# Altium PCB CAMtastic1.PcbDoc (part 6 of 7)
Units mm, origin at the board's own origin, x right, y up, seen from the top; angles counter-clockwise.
Board outline 150.22 x 135.24 mm, 5 copper layers (Top Layer, Layer 1, Mid-Layer 1, Layer 2, Bottom Layer), stack 0.461 mm thick; 0 components, 362 nets, 2885 pads, 0 vias.
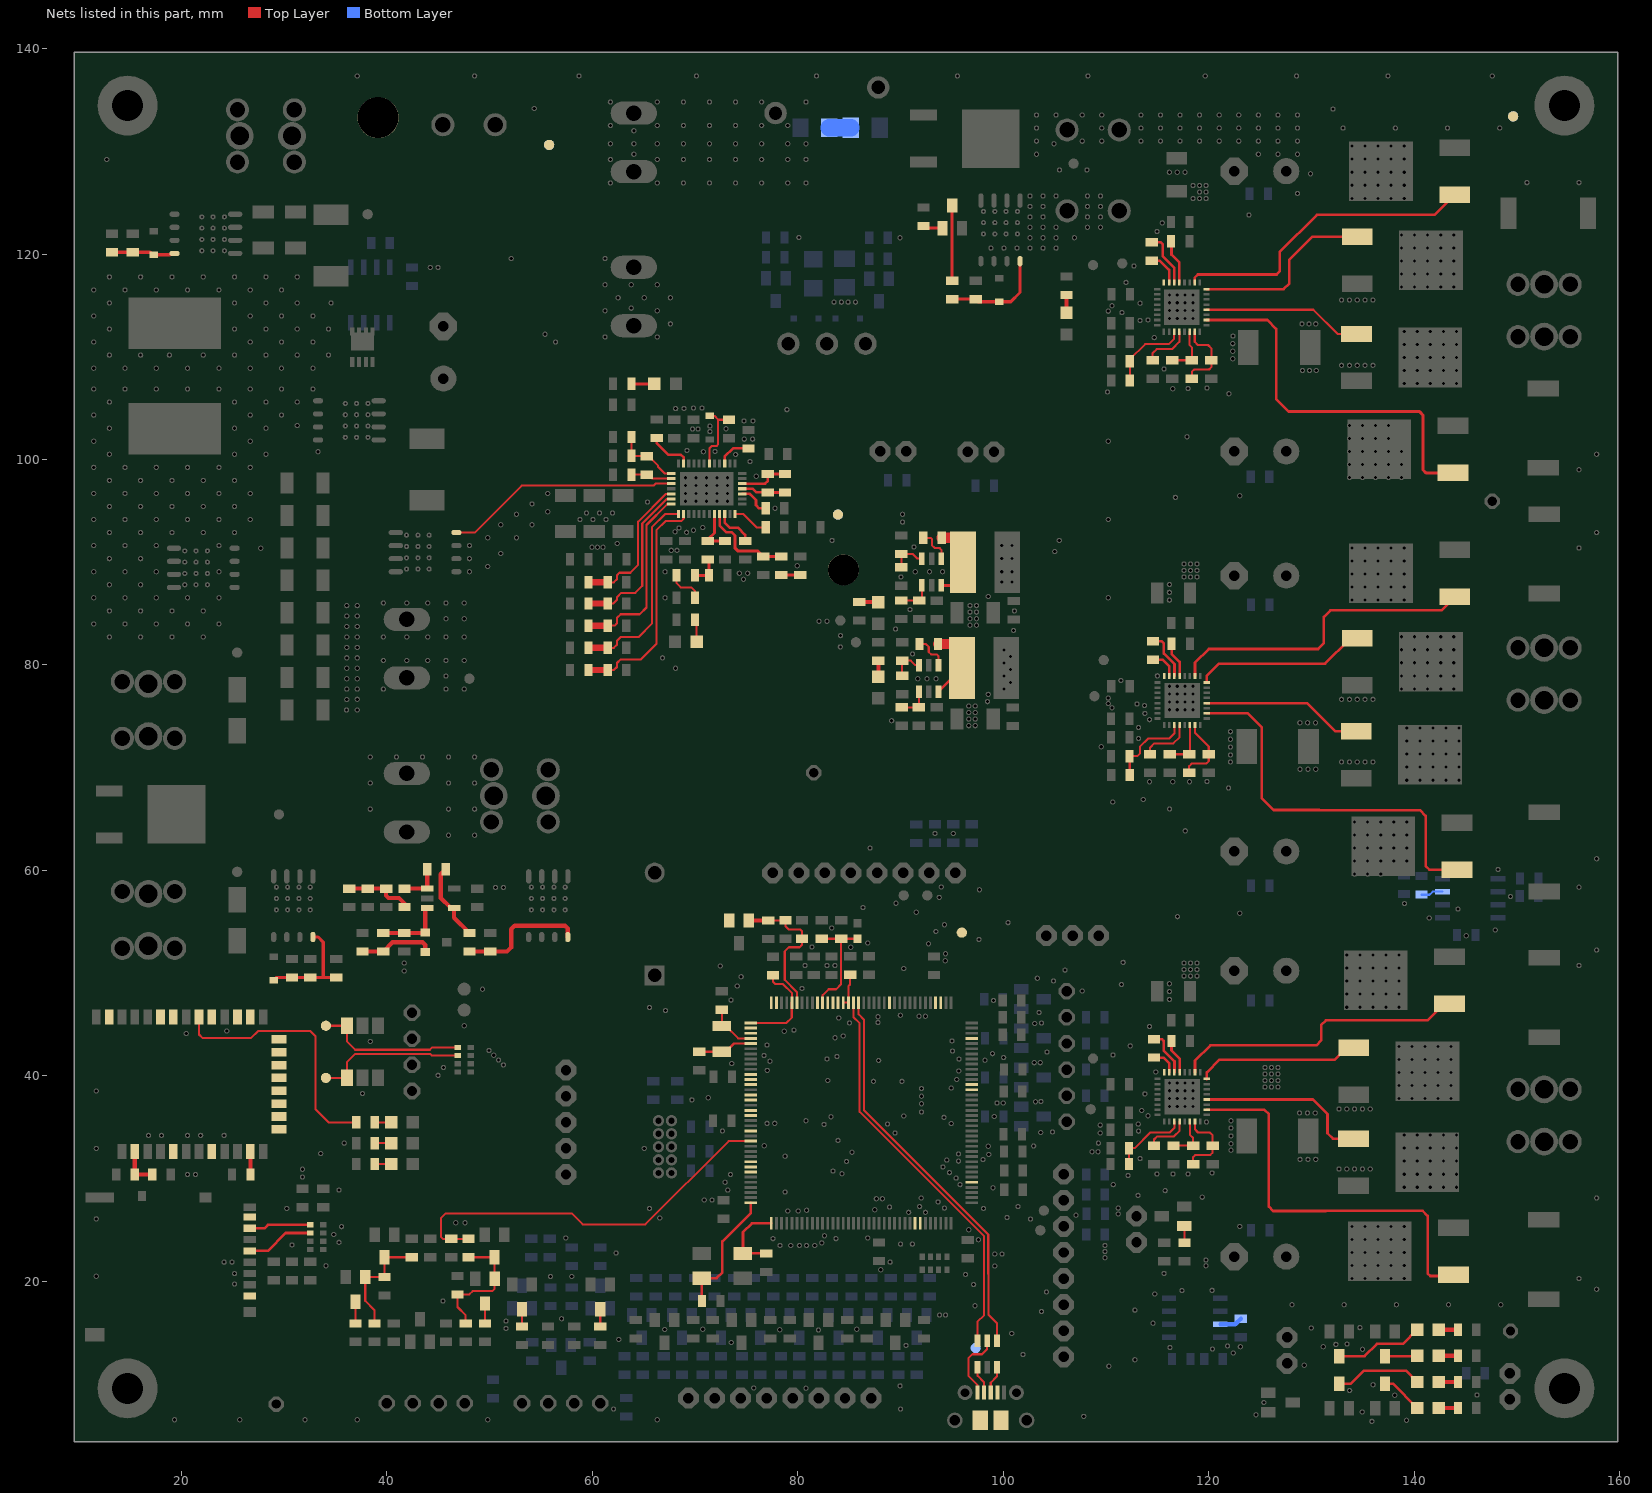
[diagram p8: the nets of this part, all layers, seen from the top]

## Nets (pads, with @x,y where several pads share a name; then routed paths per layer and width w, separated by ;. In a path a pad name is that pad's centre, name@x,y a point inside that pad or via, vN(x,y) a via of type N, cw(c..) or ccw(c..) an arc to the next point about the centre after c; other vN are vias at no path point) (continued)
$Net180: pad.1@121.125,15.824 pad.1@123.12,16.369 | length 2.2
  Bottom Layer w0.406: pad.1@121.125,15.824 122.576,15.824 pad.1@123.12,16.369
$Net181: pad.1@140.697,57.647 pad.1@142.747,57.937 | length 2.2
  Bottom Layer w0.203: pad.1@140.697,57.647 140.712,57.633 141.482,57.633 141.787,57.937 pad.1@142.747,57.937
$Net182: pad.1@83.055,132.296 pad.1@85.157,132.296 | length 2.1
  Bottom Layer w1.676: pad.1@83.055,132.296 pad.1@85.157,132.296
$Net183: pad.1@98.77,9.169 pad.1@99.379,11.628 | length 2.7
  Top Layer w0.203: pad.1@98.77,9.169 98.77,10.146 99.369,10.744 99.369,11.618 pad.1@99.379,11.628
$Net184: pad.1@97.479,11.628 pad.1@98.12,9.169 | length 2.7
  Top Layer w0.203: pad.1@97.479,11.628 97.489,11.618 97.489,10.795 98.12,10.164 pad.1@98.12,9.169
$Net185: pad.1@97.47,9.169 pad.1@98.429,14.229 | length 6.7
  Top Layer w0.203: pad.1@97.47,9.169 97.47,9.925 96.626,10.77 96.626,12.548 96.981,12.903 97.921,12.903 98.404,13.386 98.404,14.203 pad.1@98.429,14.229
$Net186: pad.1@116.378,82.08 pad.1@117.155,78.942 | length 3.5
  Top Layer w0.254: pad.1@116.378,82.08 116.389,82.069 116.389,81.051 117.155,80.285 pad.1@117.155,78.942
$Net187: pad.1@116.328,121.234 pad.1@117.13,117.233 | length 4.3
  Top Layer w0.254: pad.1@116.328,121.234 116.364,120.969 116.364,119.939 117.13,119.173 pad.1@117.13,117.233
$Net188: pad.1@70.648,20.314 pad.1@70.656,18.085 pad.1@75.417,27.648 | length 12.4
  Top Layer w0.254: pad.1@70.656,18.085 70.656,20.306 pad.1@70.648,20.314 72.083,20.314 72.648,20.879 72.648,23.901 75.417,26.67 pad.1@75.417,27.648
$Net189: pad.1@142.382,10.211 pad.1@144.242,10.211 | length 1.9
  Top Layer w0.406: pad.1@142.382,10.211 pad.1@144.242,10.211
$Net190: pad.1@142.382,15.291 pad.1@144.242,15.291 | length 1.9
  Top Layer w0.406: pad.1@142.382,15.291 pad.1@144.242,15.291
$Net191: pad.1@142.382,7.671 pad.1@144.242,7.671 | length 1.9
  Top Layer w0.406: pad.1@142.382,7.671 pad.1@144.242,7.671
$Net192: pad.1@142.382,12.751 pad.1@144.242,12.751 | length 1.9
  Top Layer w0.406: pad.1@142.382,12.751 pad.1@144.242,12.751
$Net193: pad.1@59.609,79.509 pad.1@61.493,79.509 pad.1@68.877,94.703 | length 22.5
  Top Layer w0.203: pad.1@61.493,79.509 62.089,79.509 62.386,79.807 62.386,80.188 62.742,80.543 64.723,80.543 66.222,82.042 66.222,93.116 67.111,94.005 68.635,94.005 68.889,94.259 68.889,94.691 pad.1@68.877,94.703
  Top Layer w0.61: pad.1@59.609,79.509 pad.1@61.493,79.509
$Net194: pad.1@59.609,85.986 pad.1@61.493,85.986 pad.1@67.674,96.155 | length 16
  Top Layer w0.203: pad.1@61.493,85.986 62.013,85.986 62.386,86.36 62.386,86.589 62.818,87.02 64.164,87.02 64.85,87.706 64.85,93.777 67.212,96.139 67.658,96.139 pad.1@67.674,96.155
  Top Layer w0.61: pad.1@59.609,85.986 pad.1@61.493,85.986
$Net195: pad.1@116.378,43.389 pad.1@117.155,40.353 | length 3.4
  Top Layer w0.254: pad.1@116.378,43.389 116.364,43.374 116.364,42.469 117.155,41.677 pad.1@117.155,40.353
$Net196: pad.1@59.609,88.044 pad.1@61.493,88.044 pad.1@67.674,96.655 | length 14.3
  Top Layer w0.203: pad.1@61.493,88.044 62.089,88.044 62.386,88.341 62.386,88.748 62.615,88.976 63.682,88.976 64.444,89.738 64.444,93.955 67.136,96.647 67.666,96.647 pad.1@67.674,96.655
  Top Layer w0.61: pad.1@59.609,88.044 pad.1@61.493,88.044
$Net197: pad.1@74.579,96.655 pad.1@76.879,95.247 | length 3.2
  Top Layer w0.254: pad.1@74.579,96.655 75.166,96.655 75.315,96.647 75.925,96.037 75.925,95.555 76.232,95.247 pad.1@76.879,95.247
$Net198: pad.1@59.609,83.827 pad.1@61.493,83.827 pad.1@67.674,95.655 | length 18
  Top Layer w0.203: pad.1@61.493,83.827 62.165,83.827 62.386,84.049 62.386,84.582 62.742,84.938 64.596,84.938 65.257,85.598 65.257,93.624 67.283,95.65 67.67,95.65 pad.1@67.674,95.655
  Top Layer w0.61: pad.1@59.609,83.827 pad.1@61.493,83.827
$Net199: pad.1@92.195,92.38 pad.1@93.969,90.352 | length 3.5
  Top Layer w0.203: pad.1@92.195,92.38 92.943,92.38 93.044,92.278 93.044,91.669 93.324,91.389 93.781,91.389 93.969,91.201 pad.1@93.969,90.352
$Net200: pad.1@93.969,87.752 pad.1@93.995,92.38 pad.1@96.075,89.992 | length 8.2
  Top Layer w0.203: pad.1@95.533,92.38 96.092,91.821 96.092,90.009 pad.1@96.075,89.992
  Top Layer w0.305: pad.1@93.969,87.752 95.529,87.752 96.067,88.29 96.067,89.984 pad.1@96.075,89.992
  Top Layer w1.016: pad.1@93.995,92.38 pad.1@95.533,92.38
$Net201: pad.1@112.286,71.12 pad.1@112.306,69.291 pad.1@116.655,74.142 | length 8.3
  Top Layer w0.203: pad.1@112.306,69.291 112.306,71.1 pad.1@112.286,71.12 113.034,71.12 113.288,71.374 113.288,72.034 114.101,72.847 116.133,72.847 116.655,73.37 pad.1@116.655,74.142
$Net202: pad.1@63.797,100.355 pad.1@63.797,102.184 pad.1@65.285,100.316 pad.1@67.674,98.655 | length 6.5
  Top Layer w0.203: pad.1@63.797,102.184 pad.1@63.797,100.355 65.245,100.355 pad.1@65.285,100.316 65.485,100.316 66.4,99.4 66.4,99.273 67.018,98.655 pad.1@67.674,98.655
$Net203: pad.1@69.992,84.416 pad.1@70.142,82.263 | length 2.2
  Top Layer w0.203: pad.1@69.992,84.416 70.142,84.266 pad.1@70.142,82.263
$Net204: pad.1@112.23,31.42 pad.1@112.235,32.969 pad.1@116.655,35.553 | length 7.4
  Top Layer w0.203: pad.1@112.23,31.42 112.235,31.618 pad.1@112.235,32.969 112.805,32.969 114.304,34.493 116.209,34.493 116.655,34.939 pad.1@116.655,35.553
$Net205: pad.1@63.797,98.527 pad.1@65.285,98.516 pad.1@67.674,98.155 | length 4
  Top Layer w0.203: pad.1@63.797,98.527 65.474,98.527 65.845,98.155 pad.1@67.674,98.155
$Net206: pad.1@112.311,107.696 pad.1@112.311,109.55 pad.1@116.63,112.433 | length 7.9
  Top Layer w0.203: pad.1@112.311,107.696 pad.1@112.311,109.55 112.311,109.742 113.796,111.227 116.107,111.227 116.63,111.749 pad.1@116.63,112.433
$Net207: pad.1@63.797,107.366 pad.1@66.027,107.366 | length 2.2
  Top Layer w0.305: pad.1@63.797,107.366 pad.1@66.027,107.366
$Net208: pad.1@38.801,31.42 pad.1@40.407,31.42 | length 1.6
  Top Layer w0.203: pad.1@38.801,31.42 pad.1@40.407,31.42
$Net209: pad.1@15.437,30.404 pad.1@15.456,32.631 pad.1@17.155,30.404 | length 4
  Top Layer w0.406: pad.1@15.456,32.631 15.447,32.622 15.447,30.413 pad.1@15.437,30.404 pad.1@17.155,30.404
$Net210: pad.1@45.726,60.122 pad.1@46.539,56.328 pad.1@48.027,53.91 | length 7.8
  Top Layer w0.406: pad.1@45.726,60.122 45.233,59.628 45.233,57.328 46.233,56.328 pad.1@46.539,56.328 46.539,55.398 pad.1@48.027,53.91
$Net211: pad.1@41.7,58.228 pad.1@43.927,58.228 pad.1@43.927,60.122 | length 4.1
  Top Layer w0.406: pad.1@41.7,58.228 pad.1@43.927,58.228 pad.1@43.927,60.122
$Net212: pad.1@38.801,33.452 pad.1@40.407,33.452 | length 1.6
  Top Layer w0.203: pad.1@38.801,33.452 pad.1@40.407,33.452
$Net213: pad.1@38.801,35.484 pad.1@40.407,35.484 | length 1.6
  Top Layer w0.203: pad.1@38.801,35.484 pad.1@40.407,35.484
$Net214: pad.1@21.705,45.738 pad.1@37.001,35.484 | length 25.3
  Top Layer w0.203: pad.1@21.705,45.738 21.705,44.026 22.034,43.696 26.775,43.696 27.453,44.374 32.533,44.374 33.041,43.866 33.041,36.754 34.311,35.484 pad.1@37.001,35.484
$Net215: pad.1@26.703,32.631 pad.1@26.722,30.404 | length 2.2
  Top Layer w0.406: pad.1@26.703,32.631 26.713,32.622 26.713,30.413 pad.1@26.722,30.404
$Net216: pad.1@68.192,88.722 pad.1@69.992,86.538 | length 3.5
  Top Layer w0.203: pad.1@68.192,88.722 68.192,87.962 68.601,87.554 69.617,87.554 69.992,87.178 pad.1@69.992,86.538
$Net217: pad.1@59.609,81.668 pad.1@61.493,81.668 pad.1@68.377,94.703 | length 19.9
  Top Layer w0.203: pad.1@61.493,81.668 62.089,81.668 62.386,81.966 62.386,82.372 62.742,82.728 64.495,82.728 65.79,84.023 65.79,93.396 67.085,94.691 68.365,94.691 pad.1@68.377,94.703 pad.1@68.381,94.699
  Top Layer w0.61: pad.1@59.609,81.668 pad.1@61.493,81.668
$Net218: pad.1@73.877,94.703 pad.1@76.879,93.396 | length 3.5
  Top Layer w0.203: pad.1@73.877,94.703 74.66,94.703 75.967,93.396 pad.1@76.879,93.396
$Net219: pad.1@91.84,82.042 pad.1@93.689,79.989 | length 3.5
  Top Layer w0.203: pad.1@91.84,82.042 92.46,82.042 92.739,81.763 92.739,81.255 92.968,81.026 93.501,81.026 93.705,80.823 93.705,80.004 pad.1@93.689,79.989
$Net220: pad.1@93.639,82.042 pad.1@93.689,77.389 pad.1@95.974,79.705 | length 7.9
  Top Layer w0.203: pad.1@93.689,77.389 93.689,77.421 pad.1@95.974,79.705
  Top Layer w1.016: pad.1@93.639,82.042 95.864,82.042 95.991,81.915 95.991,79.722 pad.1@95.974,79.705
$Net221: pad.1@69.992,88.722 pad.1@71.226,90.263 pad.1@71.345,88.748 | length 3
  Top Layer w0.305: pad.1@69.995,88.722 71.319,88.722 pad.1@71.345,88.748 71.345,90.255 pad.1@71.226,90.263
$Net222: pad.1@75.224,55.126 pad.1@77.118,55.129 pad.1@78.795,55.154 pad.1@79.911,47.142 pad.1@80.395,53.354 | length 14.7
  Top Layer w0.203: pad.1@77.118,55.129 78.769,55.129 pad.1@78.795,55.154 78.795,54.559 79.1,54.254 80.217,54.254 80.395,54.077 pad.1@80.395,53.354 80.395,52.756 80.166,52.527 79.125,52.527 78.719,52.121 78.719,49.352 79.911,48.16 pad.1@79.911,47.142
  Top Layer w0.406: pad.1@75.224,55.126 75.227,55.129 pad.1@77.118,55.129
$Net223: pad.1@74.648,22.714 pad.1@76.915,22.719 pad.1@77.411,25.654 | length 7.5
  Top Layer w0.254: pad.1@76.915,22.719 74.653,22.719 pad.1@74.648,22.714 74.655,22.72 74.655,24.79 75.518,25.654 pad.1@77.411,25.654
$Net224: pad.1@84.411,47.142 pad.1@84.911,47.142 pad.1@85.094,49.849 | length 3.3
  Top Layer w0.203: pad.1@84.411,47.142 pad.1@84.911,47.142 84.911,48.737 85.069,48.895 85.069,49.824 pad.1@85.094,49.849
$Net225: pad.1@114.459,121.144 pad.1@116.63,117.233 | length 5.3
  Top Layer w0.254: pad.1@114.459,121.144 114.473,121.158 115.297,121.158 115.5,120.955 115.5,119.812 116.63,118.682 pad.1@116.63,117.233
$Net226: pad.1@114.459,119.344 pad.1@116.13,117.233 | length 3.3
  Top Layer w0.254: pad.1@114.459,119.344 114.47,119.355 115.221,119.355 116.13,118.446 pad.1@116.13,117.233
$Net227: pad.1@70.413,42.353 pad.1@72.597,42.362 pad.1@75.417,43.148 | length 5.3
  Top Layer w0.203: pad.1@70.413,42.353 72.588,42.353 pad.1@72.597,42.362 72.998,42.362 73.785,43.148 pad.1@75.417,43.148
$Net228: pad.1@75.417,45.148 pad.1@77.576,49.798 pad.1@79.411,47.142 | length 9.5
  Top Layer w0.203: pad.1@75.417,45.148 78.884,45.148 79.404,45.669 79.404,47.136 pad.1@79.411,47.142 79.411,48.076 78.541,48.946 77.804,48.946 77.576,49.174 pad.1@77.576,49.798
$Net229: pad.1@72.597,44.862 pad.1@72.597,46.446 pad.1@75.417,43.648 | length 4.9
  Top Layer w0.203: pad.1@72.597,46.446 pad.1@72.597,44.862 72.973,44.862 74.187,43.648 pad.1@75.417,43.648
$Net230: pad.1@116.565,33.209 pad.1@118.47,33.209 pad.1@118.155,35.553 | length 4.4
  Top Layer w0.203: pad.1@116.565,33.209 pad.1@118.47,33.209 118.47,33.96 118.155,34.274 pad.1@118.155,35.553
$Net231: pad.1@114.561,82.319 pad.1@116.655,78.942 | length 4.7
  Top Layer w0.254: pad.1@114.561,82.319 114.563,82.321 115.399,82.321 115.627,82.093 115.627,81.102 116.655,80.074 pad.1@116.655,78.942
$Net232: pad.1@114.561,80.519 pad.1@116.155,78.942 | length 2.8
  Top Layer w0.254: pad.1@114.561,80.519 114.562,80.518 115.475,80.518 116.155,79.838 pad.1@116.155,78.942
$Net233: pad.1@71.226,92.063 pad.1@71.877,94.703 pad.1@72.905,92.061 | length 4.6
  Top Layer w0.305: pad.1@71.877,94.703 71.877,92.853 71.353,92.329 pad.1@71.226,92.063 72.902,92.063 pad.1@72.905,92.061
$Net234: pad.1@78.366,88.762 pad.1@80.217,88.759 | length 1.9
  Top Layer w0.305: pad.1@78.366,88.762 79.833,88.762 pad.1@80.217,88.759
$Net235: pad.1@72.377,94.703 pad.1@76.613,90.562 pad.1@78.366,90.562 | length 9.1
  Top Layer w0.254: pad.1@72.377,94.703 72.377,93.591 73.054,92.913 73.562,92.913 73.893,92.583
  Top Layer w0.305: 73.893,92.583 73.893,91.364 74.147,91.11 76.065,91.11 pad.1@76.613,90.562 pad.1@78.366,90.562
$Net236: pad.1@72.877,99.607 pad.1@75.191,101.081 | length 3.3
  Top Layer w0.254: pad.1@72.877,99.607 72.877,100.279 73.689,101.092 74.934,101.092 75.137,101.078 pad.1@75.191,101.081
$Net237: pad.1@114.66,33.209 pad.1@117.155,35.553 | length 4.3
  Top Layer w0.203: pad.1@114.66,33.209 114.66,33.807 114.964,34.112 116.615,34.112 117.155,34.652 pad.1@117.155,35.553
$Net238: pad.1@114.662,43.578 pad.1@116.655,40.353 | length 4.5
  Top Layer w0.254: pad.1@114.662,43.578 114.671,43.586 115.424,43.586 115.602,43.409 115.602,42.469 116.655,41.415 pad.1@116.655,40.353
$Net239: pad.1@114.662,41.778 pad.1@116.155,40.353 | length 2.6
  Top Layer w0.254: pad.1@114.662,41.778 114.668,41.783 115.602,41.783 116.155,41.23 pad.1@116.155,40.353
$Net240: pad.1@71.377,99.607 pad.1@71.432,104.249 pad.1@73.286,103.872 | length 6.9
  Top Layer w0.203: pad.1@71.378,99.609 71.378,101.067 71.632,101.321 72.089,101.321 72.242,101.473 72.242,103.81 ; pad.1@71.432,104.249 71.879,104.249 72.242,103.886 72.242,103.81 ; pad.1@73.286,103.872 72.303,103.872 72.242,103.81
  Top Layer w0.254: pad.1@71.377,99.607 pad.1@71.378,99.609
$Net241: pad.1@90.072,89.521 pad.1@90.072,90.794 pad.1@92.069,90.352 | length 3.5
  Top Layer w0.203: pad.1@90.072,89.521 pad.1@90.072,90.794 91.201,90.794 91.647,90.348 92.064,90.348 pad.1@92.069,90.352
$Net242: pad.1@90.123,75.881 pad.1@91.79,77.389 pad.1@91.774,75.881 | length 3.2
  Top Layer w0.203: pad.1@90.123,75.881 pad.1@91.774,75.881 91.79,75.896 pad.1@91.79,77.389
$Net243: pad.1@13.229,120.182 pad.1@15.261,120.182 pad.1@17.293,119.932 pad.1@19.323,120.066 | length 6.3
  Top Layer w0.305: pad.1@13.229,120.182 pad.1@15.261,120.182 16.942,120.182 17.192,119.932 pad.1@17.293,119.932 18.886,119.932 19.02,120.066 pad.1@19.323,120.066
$Net244: pad.1@90.149,78.954 pad.1@90.149,80.405 pad.1@91.79,79.989 | length 3.3
  Top Layer w0.203: pad.1@90.149,78.954 pad.1@90.149,80.405 90.16,80.416 90.987,80.416 91.414,79.989 pad.1@91.79,79.989
$Net245: pad.1@90.072,86.269 pad.1@91.825,86.269 pad.1@92.069,87.752 | length 3.3
  Top Layer w0.203: pad.1@90.072,86.269 pad.1@91.825,86.269 92.069,86.513 pad.1@92.069,87.752
$Net246: pad.1@82.325,53.354 pad.1@82.411,47.142 pad.1@84.23,53.354 pad.1@85.805,53.352 | length 11
  Top Layer w0.203: pad.1@82.325,53.354 pad.1@84.23,53.354 ; pad.1@82.411,47.142 82.411,47.863 82.986,48.438 83.722,48.438 84.18,48.895 84.18,53.024 pad.1@84.23,53.354 ; pad.1@85.805,53.352 85.879,53.354 pad.1@84.23,53.354
$Net247: pad.1@85.983,86.117 pad.1@87.837,86.115 | length 1.9
  Top Layer w0.406: pad.1@85.983,86.117 85.985,86.115 pad.1@87.837,86.115
$Net248: pad.1@37.886,20.428 pad.1@38.79,15.911 pad.1@39.755,20.433 pad.1@39.755,22.344 pad.1@42.422,22.341 | length 11.3
  Top Layer w0.203: pad.1@38.79,15.911 38.79,17.196 37.886,18.1 pad.1@37.886,20.428 39.75,20.428 pad.1@39.755,20.433 pad.1@39.755,22.344 42.419,22.344 pad.1@42.422,22.341
$Net249: pad.1@118.089,69.509 pad.1@118.655,74.142 pad.1@119.994,71.309 | length 6.8
  Top Layer w0.203: pad.1@118.089,69.509 118.089,70.155 118.343,70.409 119.765,70.409 119.994,70.637 pad.1@119.994,71.309 119.994,72.06 118.656,73.398 pad.1@118.655,74.142
$Net250: pad.1@106.151,114.271 pad.1@106.151,116.016 | length 1.7
  Top Layer w0.406: pad.1@106.151,114.271 pad.1@106.151,116.016
$Net251: pad.1@118.63,112.433 pad.1@118.343,107.863 pad.1@120.248,109.663 | length 7.5
  Top Layer w0.203: pad.1@118.343,107.863 118.343,108.534 118.571,108.763 120.019,108.763 120.248,108.991 pad.1@120.248,109.663 120.248,110.82 119.917,111.15 118.927,111.15 118.63,111.447 pad.1@118.63,112.433
$Net252: pad.1@118.47,31.409 pad.1@118.655,35.553 pad.1@120.375,33.209 | length 7.2
  Top Layer w0.203: pad.1@118.47,31.409 118.47,32.08 118.698,32.309 120.146,32.309 120.375,32.537 pad.1@120.375,33.209 120.375,34.214 120.095,34.493 118.952,34.493 118.656,34.79 pad.1@118.655,35.553
$Net253: pad.1@66.273,102.094 pad.1@68.877,99.607 | length 4.3
  Top Layer w0.254: pad.1@66.273,102.094 66.273,101.575 67.365,100.482 68.584,100.482 68.889,100.178 68.889,99.619 pad.1@68.877,99.607
$Net254: pad.1@46.257,24.141 pad.1@47.934,24.141 pad.1@75.417,33.648 | length 38.7
  Top Layer w0.203: pad.1@47.934,24.141 pad.1@46.257,24.141 45.434,24.141 45.241,24.333 45.241,26.137 45.724,26.619 57.992,26.619 59.059,25.552 65.155,25.552 73.251,33.648 pad.1@75.417,33.648
$Net255: pad.1@46.867,18.734 pad.1@47.654,15.911 pad.1@47.934,22.341 pad.1@50.474,22.344 pad.1@50.484,20.25 | length 12.6
  Top Layer w0.203: pad.1@47.654,15.911 47.654,16.713 46.867,17.501 pad.1@46.867,18.734 48.025,18.734 48.34,19.05 50.245,19.05 50.474,19.279 50.474,20.24 pad.1@50.484,20.25 50.484,22.359 pad.1@50.474,22.344 47.937,22.344 pad.1@47.934,22.341
$Net256: pad.1@116.438,109.663 pad.1@118.13,112.433 pad.1@118.343,109.663 | length 4.8
  Top Layer w0.203: pad.1@116.438,109.663 pad.1@118.343,109.663 118.343,110.922 118.13,111.134 pad.1@118.13,112.433
$Net257: pad.1@116.184,71.309 pad.1@118.089,71.309 pad.1@118.155,74.142 | length 4.8
  Top Layer w0.203: pad.1@116.184,71.309 pad.1@118.089,71.309 118.155,71.376 pad.1@118.155,74.142
$Net258: pad.1@36.343,58.228 pad.1@38.128,58.228 pad.1@39.915,58.228 pad.1@41.7,56.428 | length 6.7
  Top Layer w0.406: pad.1@36.343,58.228 pad.1@38.128,58.228 pad.1@39.915,58.228 39.915,57.566 40.153,57.328 41.169,57.328 41.7,56.796 pad.1@41.7,56.428
$Net259: pad.1@53.141,15.607 pad.1@53.141,17.291 | length 1.7
  Top Layer w0.203: pad.1@53.141,15.607 pad.1@53.141,17.291
$Net260: pad.1@28.977,49.32 pad.1@30.755,49.57 pad.1@32.533,49.57 pad.1@32.787,53.518 pad.1@35.073,49.57 | length 10.9
  Top Layer w0.305: pad.1@28.977,49.32 29.227,49.57 pad.1@30.755,49.57 pad.1@32.533,49.57 33.803,49.57 ; pad.1@32.787,53.518 33.295,53.518 33.803,53.01 33.803,49.57 ; pad.1@35.073,49.57 33.803,49.57
$Net261: pad.1@37.613,52.11 pad.1@39.645,52.11 pad.1@43.725,52.06 | length 7.3
  Top Layer w0.406: pad.1@37.613,52.11 pad.1@39.645,52.11 40.544,53.01 43.455,53.01 43.725,52.74 pad.1@43.725,52.06
$Net262: pad.1@36.936,15.911 pad.1@36.936,18.028 | length 2.1
  Top Layer w0.203: pad.1@36.936,15.911 pad.1@36.936,18.028
$Net263: pad.1@39.645,53.91 pad.1@41.677,53.91 pad.1@43.725,53.96 pad.1@43.927,56.328 | length 6.6
  Top Layer w0.406: pad.1@39.645,53.91 pad.1@41.677,53.91 43.675,53.91 pad.1@43.725,53.96 43.725,56.126 pad.1@43.927,56.328
$Net264: pad.1@48.027,52.11 pad.1@50.059,52.11 pad.1@57.605,53.518 | length 12.6
  Top Layer w0.406: pad.1@48.027,52.11 pad.1@50.059,52.11 51.699,52.11 52.091,52.502 52.091,54.28 52.43,54.619 57.339,54.619 57.605,54.354 pad.1@57.605,53.518
$Net265: pad.1@49.534,15.911 pad.1@49.534,17.85 | length 1.9
  Top Layer w0.203: pad.1@49.534,15.911 pad.1@49.534,17.85
$Net266: pad.1@60.761,15.607 pad.1@60.761,17.291 | length 1.7
  Top Layer w0.203: pad.1@60.761,15.607 pad.1@60.761,17.291
$Net267: pad.1@95.017,115.61 pad.1@97.303,115.61 pad.1@99.589,115.36 pad.1@101.621,119.304 | length 10.1
  Top Layer w0.305: pad.1@95.017,115.61 pad.1@97.303,115.61 97.553,115.36 pad.1@99.589,115.36 100.724,115.36 101.621,116.256 pad.1@101.621,119.304
$Net268: pad.1@95.017,117.41 pad.1@95.017,124.722 | length 7.3
  Top Layer w0.305: pad.1@95.006,117.399 pad.1@95.017,117.41 pad.1@95.017,124.722
$Net269: pad.1@92.223,122.722 pad.1@94.067,122.522 | length 1.9
  Top Layer w0.305: pad.1@92.223,122.722 92.423,122.522 pad.1@94.067,122.522
  Top Layer w0.61: pad.1@94.063,122.519 pad.1@94.067,122.522
$Net270: pad.1@114.533,109.663 pad.1@117.13,112.433 | length 4.7
  Top Layer w0.203: pad.1@114.533,109.663 114.533,110.363 114.914,110.744 116.412,110.744 117.13,111.462 pad.1@117.13,112.433
$Net271: pad.1@87.837,78.85 pad.1@87.837,80.405 | length 1.6
  Top Layer w0.406: pad.1@87.837,78.85 pad.1@87.837,80.405
$Net272: pad.1@74.579,97.155 pad.1@77.07,96.788 pad.1@78.747,96.788 | length 4.3
  Top Layer w0.254: pad.1@74.579,97.155 75.43,97.155 75.594,97.155 75.95,96.799 pad.1@77.07,96.788 pad.1@78.747,96.788
$Net273: pad.1@74.579,97.655 pad.1@77.07,98.588 pad.1@78.747,98.588 | length 4.9
  Top Layer w0.254: pad.1@74.579,97.655 76.806,97.655 77.068,97.917 pad.1@77.07,98.588 pad.1@78.747,98.588
$Net274: pad.1@114.279,71.309 pad.1@117.155,74.142 | length 5.1
  Top Layer w0.203: pad.1@114.279,71.309 114.279,71.958 114.685,72.365 116.539,72.365 117.155,72.981 pad.1@117.155,74.142
$Net275: pad.1@72.877,94.703 pad.1@74.861,92.061 | length 3.9
  Top Layer w0.254: pad.1@72.877,94.703 72.877,93.853 73.359,93.37 74.147,93.37 74.858,92.659 74.858,92.089 pad.1@74.861,92.061
$Net276: pad.1@117.614,25.39 pad.1@117.631,23.76 | length 1.6
  Top Layer w0.203: pad.1@117.614,25.39 117.614,23.778 pad.1@117.631,23.76
$Net277: pad.1@118.63,117.233 pad.1@143.943,125.782 | length 30.2
  Top Layer w0.254: pad.1@118.63,117.233 118.63,117.711 118.927,118.008 126.598,118.008 126.902,118.313 126.902,120.193 130.535,123.825 141.987,123.825 pad.1@143.943,125.782
$Net278: pad.1@119.78,116.583 pad.1@134.444,121.69 | length 18.1
  Top Layer w0.203: pad.1@134.443,121.691 pad.1@134.444,121.69 pad.1@134.446,121.693
  Top Layer w0.254: pad.1@119.78,116.583 127.281,116.583 127.842,117.145 127.842,119.456 130.077,121.691 pad.1@134.443,121.691
$Net279: pad.1@119.805,76.292 pad.1@134.347,73.544 | length 16.1
  Top Layer w0.203: pad.1@134.336,73.533 pad.1@134.347,73.544
  Top Layer w0.254: pad.1@119.805,76.292 129.579,76.292 132.338,73.533 pad.1@134.336,73.533 ; pad.1@134.082,73.279 pad.1@134.347,73.544 pad.1@134.358,73.533
$Net280: pad.1@119.78,114.583 pad.1@134.373,112.216 | length 15.6
  Top Layer w0.203: 130.175,114.583 132.541,112.217 pad.1@134.372,112.217
  Top Layer w0.254: pad.1@119.78,114.583 130.175,114.583 ; pad.1@134.372,112.217 pad.1@134.373,112.216
$Net281: pad.1@119.805,78.292 pad.1@134.444,82.587 | length 16.8
  Top Layer w0.254: pad.1@119.805,78.292 119.805,78.956 120.987,80.137 131.322,80.137 133.684,82.499 134.356,82.499 pad.1@134.444,82.587 pad.1@134.446,82.584
$Net282: pad.1@119.805,75.292 pad.1@144.152,60.06 | length 37.6
  Top Layer w0.203: 130.763,65.888 130.789,65.862
  Top Layer w0.254: pad.1@119.805,75.292 123.797,75.292 125.15,73.939 125.15,67.031 126.293,65.888 130.763,65.888 ; 130.789,65.862 140.542,65.862 141.101,65.303 141.101,60.427 141.457,60.071 144.14,60.071 pad.1@144.152,60.06
$Net283: pad.1@119.78,113.583 pad.1@143.771,98.705 | length 37.3
  Top Layer w0.254: pad.1@119.78,113.583 125.689,113.583 126.547,112.725 126.547,105.893 127.766,104.673 140.491,104.673 140.517,104.648
  Top Layer w0.305: 140.517,104.648 140.847,104.318 140.847,98.984 141.126,98.704 143.77,98.704 pad.1@143.771,98.705
$Net284: pad.1@118.655,78.942 pad.1@143.943,86.628 | length 30.7
  Top Layer w0.254: pad.1@118.655,78.942 118.656,80.219 119.996,81.559 130.636,81.559 131.195,82.118 131.195,84.684 131.83,85.319 142.634,85.319 pad.1@143.943,86.628
$Net285: pad.1@119.805,36.703 pad.1@143.821,20.646 | length 39.3
  Top Layer w0.203: 131.373,26.848 131.398,26.873
  Top Layer w0.254: pad.1@119.805,36.703 125.404,36.703 125.836,36.271 125.836,27.28 126.267,26.848 131.373,26.848 ; 131.398,26.873 140.796,26.873 141.304,26.365 141.304,20.777 141.558,20.523 143.699,20.523 pad.1@143.821,20.646 pad.1@143.817,20.65
$Net286: pad.1@119.805,37.703 pad.1@134.093,33.888 | length 17
  Top Layer w0.254: pad.1@119.805,37.703 130.119,37.703 131.551,36.271 131.551,34.417 132.084,33.884 134.089,33.884 pad.1@134.093,33.888 pad.1@134.098,33.884
$Net287: pad.1@118.655,40.353 pad.1@143.435,47.036 | length 29.1
  Top Layer w0.254: pad.1@118.655,40.353 118.656,41.484 120.149,42.977 130.458,42.977 130.941,43.459 130.941,44.958 131.398,45.415 141.304,45.415 142.828,46.939 143.338,46.939 pad.1@143.435,47.036
$Net288: pad.1@119.805,39.703 pad.1@134.114,42.753 | length 15.9
  Top Layer w0.254: pad.1@119.805,39.703 119.805,40.348 121.038,41.58 132.262,41.58 133.176,42.494 133.855,42.494 pad.1@134.114,42.753
$Net289: pad.1@85.411,47.142 pad.1@97.479,14.229 | length 38.5
  Top Layer w0.203: pad.1@85.411,47.142 85.411,45.708 86.008,45.11 86.008,36.5 98.124,24.384 98.124,16.713 97.464,16.053 97.464,14.244 pad.1@97.479,14.229
$Net290: pad.1@85.911,47.142 pad.1@99.379,14.229 | length 38.6
  Top Layer w0.203: pad.1@85.911,47.142 85.911,45.995 86.415,45.491 86.415,36.678 98.531,24.562 98.556,16.764 99.369,15.951 99.369,14.326 99.369,14.239 pad.1@99.379,14.229 pad.1@99.293,14.326
$Net291: pad.1@132.696,12.719 pad.1@140.282,15.291 | length 8.7
  Top Layer w0.254: pad.1@132.696,12.719 135.151,12.719 136.351,13.919 138.911,13.919 pad.1@140.282,15.291
$Net292: pad.1@132.696,10.039 pad.1@140.282,10.211 | length 8.6
  Top Layer w0.254: pad.1@132.696,10.039 133.817,10.039 135.081,11.303 139.19,11.303 pad.1@140.282,10.211
$Net293: pad.1@137.141,12.719 pad.1@140.282,12.751 | length 3.2
  Top Layer w0.254: pad.1@137.141,12.719 140.251,12.719 pad.1@140.282,12.751
$Net294: pad.1@137.141,10.039 pad.1@140.282,7.671 | length 4.1
  Top Layer w0.254: pad.1@137.141,10.039 137.914,10.039 pad.1@140.282,7.671
$Net295: pad.1@46.757,92.888 pad.1@67.674,97.655 | length 22.9
  Top Layer w0.203: pad.1@46.757,92.888 48.535,92.888 53.107,97.46 65.942,97.46 66.146,97.663 67.666,97.663 pad.1@67.674,97.655
$Net296: pad.1@34.057,39.802 pad.1@36.089,39.802 pad.1@46.893,41.98 | length 14.8
  Top Layer w0.203: pad.1@34.057,39.802 pad.1@36.089,39.802 36.089,41.326 36.901,42.139 44.206,42.139 44.365,41.98 pad.1@46.893,41.98
$Net297: pad.1@34.057,44.882 pad.1@36.089,44.882 pad.1@46.893,42.78 | length 14.8
  Top Layer w0.203: pad.1@34.057,44.882 pad.1@36.089,44.882 36.089,43.358 36.901,42.545 44.169,42.545 44.403,42.78 pad.1@46.893,42.78
$Net298: pad.1@26.642,22.968 pad.1@32.533,24.708 | length 6.6
  Top Layer w0.254: pad.1@26.642,22.968 28.398,22.968 30.139,24.708 pad.1@32.533,24.708
$Net299: pad.1@26.642,25.168 pad.1@32.533,25.508 | length 6
  Top Layer w0.254: pad.1@26.642,25.168 28.059,25.168 28.398,25.508 pad.1@32.533,25.508
$Net300: pad.1@83.9,94.64
$Net301: pad.1@97.303,13.513
$Net302: pad.1@55.786,130.625
$Net303: pad.1@149.623,133.401
$Net304: 
$Net305: 
$Net306: pad.1@97.77,6.469
$Net307: pad.1@99.77,6.469
$Net308: pad.1@99.42,9.169
$Net309: pad.1@115.655,78.942
$Net310: pad.1@115.63,117.233
$Net311: pad.1@115.655,40.353
$Net312: pad.1@96.905,43.648
$Net313: pad.1@96.905,39.148
$Net314: pad.1@96.905,38.648
$Net315: pad.1@96.905,29.648
$Net316: pad.1@75.417,30.648
$Net317: pad.1@75.417,31.148
$Net318: pad.1@75.417,31.648
$Net319: pad.1@75.417,34.648
$Net320: pad.1@75.417,36.148
$Net321: pad.1@75.417,36.648
$Net322: pad.1@75.417,37.648
$Net323: pad.1@75.417,38.148
$Net324: pad.1@75.417,39.148
$Net325: pad.1@75.417,39.648
$Net326: pad.1@75.417,40.148
$Net327: pad.1@75.417,44.148
$Net328: pad.1@75.417,44.648
$Net329: pad.1@91.911,25.654
$Net330: pad.1@91.411,25.654
$Net331: pad.1@77.411,47.142
$Net332: pad.1@77.911,47.142
$Net333: pad.1@81.911,47.142
$Net334: pad.1@82.911,47.142
$Net335: pad.1@83.411,47.142
$Net336: pad.1@83.911,47.142
$Net337: pad.1@88.911,47.142
$Net338: pad.1@93.411,47.142
$Net339: pad.1@93.911,47.142
$Net340: pad.1@73.324,55.126
$Net341: pad.1@55.786,130.625
$Net342: pad.1@95.953,53.95
$Net343: pad.1@83.9,94.64
$Net344: pad.1@149.623,133.401
$Net345: pad.1@19.205,32.631
$Net346: pad.1@22.954,32.631
$Net347: pad.1@26.703,45.738
$Net348: pad.1@25.454,45.738
$Net349: pad.1@22.954,45.738
$Net350: pad.1@19.205,45.738
$Net351: pad.1@17.956,45.738
$Net352: pad.1@12.957,45.738
$Net353: pad.1@29.485,34.803
$Net354: pad.1@29.485,36.053
$Net355: pad.1@29.485,37.302
$Net356: pad.1@29.485,38.552
$Net357: pad.1@29.485,39.802
$Net358: pad.1@29.485,41.051
$Net359: pad.1@29.485,42.301
$Net360: pad.1@29.485,43.566
$Net361: pad.1@26.642,18.568
$Net362: pad.1@26.642,26.268
$Net363: pad.1@39.137,133.274
$Net364: pad.1@84.435,89.258
copper on no net: | length 4.7
  Top Layer w0.2: 157.179,13.995 157.093,14.082 157.611,14.082 ; 157.611,13.995 157.611,14.168
  Layer 1 w0.2: 157.073,16.459 156.986,16.546 156.986,16.718 157.073,16.805 157.159,16.805 157.246,16.718 ; 157.246,16.632 157.246,16.718 ; 157.418,16.459 157.505,16.546 157.505,16.718 157.418,16.805 157.332,16.805 157.246,16.718
  Layer 2 w0.2: 157.179,15.138 157.093,15.225 157.093,15.397 157.179,15.484 157.266,15.484 157.611,15.138 157.611,15.484
  Bottom Layer w0.2: 157.352,17.719 157.352,17.374 157.093,17.633 157.611,17.633

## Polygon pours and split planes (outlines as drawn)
$Net0 on Bottom Layer "Bottom Layer-$Net0 12" (solid, pour order 2594): 101 vertices, not listed, extent 10.952,5.776 158.417,138.24
$Net6 on Bottom Layer "Bottom Layer-$Net6" (solid, pour order 2592): 51.922,15.164 51.261,15.164 51.261,16.167 51.284,16.285 51.922,16.285
$Net6 on Bottom Layer "Bottom Layer-$Net6 1" (solid, pour order 2590): 111.51,26.213 110.85,26.213 110.85,27.483 111.51,27.483
$Net156 on Bottom Layer "Bottom Layer-$Net156" (solid, pour order 2588): 25.421,73.838 25.421,51.74 24.659,50.978 13.229,50.978 12.721,51.486 12.721,54.026 12.975,54.28 22.627,54.28 23.389,55.042 23.389,70.536 22.627,71.298 12.975,71.298 12.975,71.806 12.975,74.6 24.659,74.6
$Net1 on Bottom Layer "Bottom Layer-$Net1" (solid, pour order 2586): 57.933,55.296 53.361,55.296 53.361,71.806 57.933,71.806
$Net157 on Bottom Layer "Bottom Layer-$Net157" (solid, pour order 2584): 21.357,55.804 12.213,55.804 12.213,60.122 21.357,60.122
$Net80 on Bottom Layer "Bottom Layer-$Net80" (solid, pour order 2582): 52.599,71.552 52.599,61.392 34.057,61.392 34.057,68.504 37.105,71.552
$Net107 on Bottom Layer "Bottom Layer-$Net107" (solid, pour order 2578): 137.113,118.747 137.113,106.958 136.404,106.248 129.441,106.248 128.731,106.958 128.731,118.747 129.441,119.456 136.404,119.456
$Net7 on Bottom Layer "Bottom Layer-$Net7" (solid, pour order 2576): 156.747,35.003 156.747,23.315 155.86,22.428 142.649,22.428 141.939,23.138 141.939,26.948 141.378,27.508 137.823,27.508 137.113,28.218 137.113,34.927 137.823,35.636 156.114,35.636
$Net9 on Bottom Layer "Bottom Layer-$Net9" (solid, pour order 2574): 18 vertices, not listed, extent 128.223,27.508 136.859,40.716
$Net8 on Bottom Layer "Bottom Layer-$Net8" (solid, pour order 2572): 26 vertices, not listed, extent 137.113,36.398 156.671,53.162
$Net0 on Bottom Layer "Bottom Layer-$Net0" (solid, pour order 2570): 53 vertices, not listed, extent 138.403,56.521 139.945,58.09
$Net0 on Bottom Layer "Bottom Layer-$Net0 1" (solid, pour order 2568): 57 vertices, not listed, extent 140.277,44.94 143.907,58.991
$Net102 on Bottom Layer "Bottom Layer-$Net102" (solid, pour order 2566): 17 vertices, not listed, extent 137.367,62.052 156.849,78.562
$Net101 on Bottom Layer "Bottom Layer-$Net101" (solid, pour order 2564): 18 vertices, not listed, extent 128.223,67.132 137.113,80.34
$Net103 on Bottom Layer "Bottom Layer-$Net103" (solid, pour order 2562): 21 vertices, not listed, extent 137.367,76.276 156.824,92.786
$Net10 on Bottom Layer "Bottom Layer-$Net10" (solid, pour order 2560): 137 vertices, not listed, extent 97.159,19.888 139.907,134.366
$Net105 on Bottom Layer "Bottom Layer-$Net105" (solid, pour order 2558): 156.671,113.641 156.671,102.995 155.86,102.184 138.838,102.184 138.129,102.894 138.129,103.134 138.138,103.155 138.16,103.327 138.138,103.5 138.129,103.52 138.129,113.667 138.838,114.376 155.936,114.376
$Net106 on Bottom Layer "Bottom Layer-$Net106" (solid, pour order 2556): 32 vertices, not listed, extent 138.155,114.859 156.697,131.75
$Net158 on Bottom Layer "Bottom Layer-$Net158" (solid, pour order 2554): 21.357,76.124 12.213,76.124 12.213,80.696 21.357,80.696
$Net111 on Bottom Layer "Bottom Layer-$Net111" (solid, pour order 2552): 64.283,95.682 57.171,95.682 49.043,87.554 49.043,77.14 39.137,77.14 39.137,87.808 44.217,87.808 45.995,89.586 45.995,92.126 48.789,92.126 53.869,97.206 64.283,97.206
$Net2 on Bottom Layer "Bottom Layer-$Net2" (solid, pour order 2548): 45.741,94.92 44.725,93.904 44.725,88.824 39.899,88.824 39.899,93.396 41.931,95.428 41.931,96.952 45.741,96.952
$Net6 on Bottom Layer "Bottom Layer-$Net6 2" (solid, pour order 2546): 94.721,16.358 93.451,16.358 93.451,17.018 94.721,17.018
$Net0 on Bottom Layer "Bottom Layer-$Net0 2" (solid, pour order 2544): 22 vertices, not listed, extent 86.38,19.69 90.473,22.195
$Net0 on Bottom Layer "Bottom Layer-$Net0 3" (solid, pour order 2542): 97.551,24.591 97.506,24.456 97.407,24.437 97.272,24.347 97.183,24.212 97.159,24.092 97.053,24.044 97.029,24.042 94.449,26.621 94.445,26.642 94.473,26.778 94.556,26.834 94.579,26.868 95.274,26.868
$Net0 on Bottom Layer "Bottom Layer-$Net0 4" (solid, pour order 2540): 268 vertices, not listed, extent 70.327,19.69 94.426,28.418
$Net0 on Bottom Layer "Bottom Layer-$Net0 5" (solid, pour order 2538): 18 vertices, not listed, extent 78.713,28.761 89.229,34.183
$Net0 on Bottom Layer "Bottom Layer-$Net0 6" (solid, pour order 2536): 65 vertices, not listed, extent 94.498,29.12 98.299,33.447
$Net6 on Bottom Layer "Bottom Layer-$Net6 3" (solid, pour order 2534): 104.042,37.161 104.042,37.16 102.855,37.16 102.855,37.821 104.042,37.821
$Net6 on Bottom Layer "Bottom Layer-$Net6 4" (solid, pour order 2532): 103.966,40.945 102.855,40.945 102.855,41.605 103.966,41.605
$Net6 on Bottom Layer "Bottom Layer-$Net6 5" (solid, pour order 2530): 103.966,44.78 102.855,44.78 102.855,45.441 103.966,45.441
$Net0 on Bottom Layer "Bottom Layer-$Net0 7" (solid, pour order 2528): 67 vertices, not listed, extent 98.398,43.922 105.663,47.214
$Net0 on Bottom Layer "Bottom Layer-$Net0 8" (solid, pour order 2526): 24 vertices, not listed, extent 79.714,48.553 84.088,51.176
$Net0 on Bottom Layer "Bottom Layer-$Net0 9" (solid, pour order 2524): 17 vertices, not listed, extent 83.148,51.008 92.024,54.988
$Net3 on Bottom Layer "Bottom Layer-$Net3" (solid, pour order 2522): 68.093,119.558 68.093,110.922 60.514,110.922 59.965,111.472 59.965,119.558 60.727,120.32 67.331,120.32
$Net0 on Bottom Layer "Bottom Layer-$Net0 10" (solid, pour order 2520): 27 vertices, not listed, extent 119.544,11.359 123.967,14.192
$Net6 on Bottom Layer "Bottom Layer-$Net6 6" (solid, pour order 2518): 120.044,21.158 119.384,21.158 119.384,22.428 120.044,22.428
$Net0 on Bottom Layer "Bottom Layer-$Net0 11" (solid, pour order 2516): 80 vertices, not listed, extent 113.877,31.011 120.688,68.01
$Net19 on Bottom Layer "Bottom Layer-$Net19" (solid, pour order 2514): 85.873,114.732 83.079,114.732 83.079,117.69 83.168,117.78 85.873,117.78
$Net6 on Bottom Layer "Bottom Layer-$Net6 7" (solid, pour order 2512): 45.487,118.288 43.709,118.288 43.709,119.304 45.487,119.304
$Net5 on Bottom Layer "Bottom Layer-$Net5" (solid, pour order 2510): 113.305,120.066 97.303,120.066 97.303,126.416 113.305,126.416
$Net117 on Bottom Layer "Bottom Layer-$Net117" (solid, pour order 2508): 81.301,130.734 81.301,126.416 61.235,126.416 61.235,135.306 81.301,135.306
$Net160 on Bottom Layer "Bottom Layer-$Net160" (solid, pour order 2506): 27.707,126.924 23.135,126.924 23.135,136.83 27.707,136.83
$Net109 on Bottom Layer "Bottom Layer-$Net109" (solid, pour order 2188): 33.295,126.924 28.723,126.924 28.723,136.83 33.295,136.83
$Net4 on Bottom Layer "Bottom Layer-$Net4" (solid, pour order 2186): 17 vertices, not listed, extent 10.952,81.204 34.311,107.366
$Net110 on Bottom Layer "Bottom Layer-$Net110" (solid, pour order 2184): 35.835,108.382 10.952,108.382 10.952,119.558 35.835,119.558
$Net100 on Bottom Layer "Bottom Layer-$Net100" (solid, pour order 2182): 89.683,137.592 89.683,130.988 86.635,130.988 86.635,134.29 86.127,134.798 86.127,137.592 86.635,138.1 89.175,138.1
no net on Bottom Overlay (solid): 149.097,59.202 149.397,59.002 149.397,59.402 149.097,59.202
no net on Bottom Overlay (solid): 40.274,112.352 40.075,112.052 40.475,112.052 40.274,112.352
$Net0 on Top Layer "Top Layer-$Net0 9" (solid, pour order 2966): 3865 vertices, not listed, extent 10.952,5.776 158.417,138.24
$Net6 on Top Layer "Top Layer-$Net6" (solid, pour order 2964): 48.027,25.375 46.334,25.375 46.334,26.035 48.027,26.035
$Net6 on Top Layer "Top Layer-$Net6 1" (solid, pour order 2962): 25.421,21.26 23.643,21.26 23.643,22.276 25.421,22.276
$Net10 on Top Layer "Top Layer-$Net10" (solid, pour order 2960): 139.933,25.945 139.909,19.889 135.948,19.863 125.62,19.863 124.896,20.587 124.896,25.285 125.62,26.01 130.382,26.01 139.843,26.035
$Net6 on Top Layer "Top Layer-$Net6 2" (solid, pour order 2958): 21.865,29.896 20.087,29.896 20.087,30.912 21.865,30.912
$Net6 on Top Layer "Top Layer-$Net6 3" (solid, pour order 2956): 32.279,29.642 31.263,29.642 31.263,31.42 32.279,31.42
$Net6 on Top Layer "Top Layer-$Net6 4" (solid, pour order 2954): 77.999,35.052 76.661,35.052 76.661,35.712 77.999,35.712
$Net10 on Top Layer "Top Layer-$Net10 1" (solid, pour order 2952): 140.187,46.19 140.096,46.1 136.784,46.126 124.848,46.126 124.848,48.998 124.896,51.844 124.896,52.412 124.986,52.502 140.187,52.502
$Net156 on Top Layer "Top Layer-$Net156" (solid, pour order 2950): 32.025,54.026 32.025,52.502 32.533,51.994 33.295,51.994 33.295,50.724 12.467,50.724 11.705,51.486 11.705,53.772 12.467,54.534 31.517,54.534
$Net19 on Top Layer "Top Layer-$Net19" (solid, pour order 2948): 42.185,49.708 41.169,49.708 41.169,51.486 42.185,51.486
$Net1 on Top Layer "Top Layer-$Net1" (solid, pour order 2946): 57.933,55.568 53.361,55.568 53.361,71.806 57.933,71.806
$Net80 on Top Layer "Top Layer-$Net80" (solid, pour order 2944): 52.599,61.392 16.531,61.392 16.531,68.504 34.057,68.504 37.105,71.552 52.599,71.552
$Net19 on Top Layer "Top Layer-$Net19 1" (solid, pour order 2942): 51.837,57.836 50.059,57.836 50.059,58.852 51.837,58.852
$Net156 on Top Layer "Top Layer-$Net156 1" (solid, pour order 2940): 26.437,71.552 13.483,71.552 12.975,72.06 12.975,74.6 13.483,75.108 26.437,75.108
$Net6 on Top Layer "Top Layer-$Net6 5" (solid, pour order 2938): 83.333,83.744 81.555,83.744 81.555,84.76 83.333,84.76
$Net10 on Top Layer "Top Layer-$Net10 2" (solid, pour order 2596): 140.187,59.068 140.096,58.978 136.784,59.004 124.848,59.004 124.848,61.876 124.896,64.722 124.896,65.29 124.986,65.38 140.187,65.38
$Net102 on Top Layer "Top Layer-$Net102" (solid, pour order 2936): 17 vertices, not listed, extent 137.367,62.052 156.849,78.562
$Net101 on Top Layer "Top Layer-$Net101" (solid, pour order 2934): 37 vertices, not listed, extent 128.223,67.132 137.113,80.34
$Net103 on Top Layer "Top Layer-$Net103" (solid, pour order 2932): 30 vertices, not listed, extent 137.367,76.276 156.824,92.786
$Net100 on Top Layer "Top Layer-$Net100" (solid, pour order 2930): 119.257,89.882 119.257,81.898 118.74,81.382 117.716,81.382 117.458,81.64 117.225,81.873 117.225,88.646 117.225,89.882 117.488,90.145 118.994,90.145
$Net10 on Top Layer "Top Layer-$Net10 3" (solid, pour order 2928): 125.543,92.088 126.787,92.069 128.031,92.068 129.275,92.085 129.897,92.1 139.958,92.1 139.958,85.707 131.83,85.707 131.722,85.686 124.95,85.674 124.921,92.014 125.012,92.102
$Net6 on Top Layer "Top Layer-$Net6 6" (solid, pour order 2926): 101.68,85.827 100.359,85.827 100.359,86.191 99.911,86.639 99.301,86.639 99.14,86.8 99.14,93.04 101.68,93.04
$Net3 on Top Layer "Top Layer-$Net3" (solid, pour order 2924): 93.044,76.826 93.289,76.581 93.899,76.581 94.102,76.378 97.531,76.378 97.769,76.141 97.769,73.661 94.76,73.635 94.67,73.724 94.67,74.752 92.841,74.752 92.841,76.132 92.435,76.539 92.435,78.003 93.044,78.003
$Net19 on Top Layer "Top Layer-$Net19 2" (solid, pour order 2922): 101.579,75.463 100.258,75.463 100.258,75.828 99.809,76.276 99.2,76.276 99.039,76.437 99.039,82.677 101.579,82.677
$Net220 on Top Layer "Top Layer-$Net220" (solid, pour order 2920): 97.083,78.376 97.083,76.632 94.551,76.632 94.399,76.784 93.425,76.784 93.425,78.003 93.993,78.003 94.653,78.664 96.795,78.664
$Net3 on Top Layer "Top Layer-$Net3 1" (solid, pour order 2918): 93.324,87.19 93.645,86.868 94.255,86.868 94.484,86.639 97.699,86.588 97.845,86.491 97.845,83.998 94.949,83.998 94.949,85.115 92.714,85.115 92.714,88.367 93.324,88.367
$Net200 on Top Layer "Top Layer-$Net200" (solid, pour order 2916): 97.337,88.739 97.337,86.995 94.805,86.995 94.653,87.147 93.679,87.147 93.679,88.367 94.247,88.367 94.907,89.027 97.049,89.027
$Net6 on Top Layer "Top Layer-$Net6 7" (solid, pour order 2914): 90.699,93.396 89.683,93.396 89.683,95.174 90.699,95.174
$Net160 on Top Layer "Top Layer-$Net160" (solid, pour order 2912): 27.707,126.924 23.135,126.924 20.341,124.13 20.341,120.828 20.087,120.574 18.563,120.574 17.801,121.336 14.499,121.336 14.499,122.86 23.135,131.496 23.135,136.322 27.707,136.322
$Net10 on Top Layer "Top Layer-$Net10 4" (solid, pour order 2910): 23 vertices, not listed, extent 97.54,124.765 140.187,134.366
$Net117 on Top Layer "Top Layer-$Net117" (solid, pour order 2908): 81.301,132.004 81.301,126.416 61.235,126.416 61.235,135.306 81.301,135.306
$Net123 on Top Layer "Top Layer-$Net123" (solid, pour order 2666): 94.97,7.419 96.47,7.419 96.47,5.519 94.97,5.519 94.871,5.519 94.687,5.595 94.546,5.736 94.47,5.92 94.47,6.019 94.47,6.919 94.47,7.019 94.546,7.203 94.687,7.343 94.871,7.419
$Net124 on Top Layer "Top Layer-$Net124" (solid, pour order 2664): 102.853,7.343 102.994,7.203 103.07,7.019 103.07,6.919 103.07,6.019 103.07,5.92 102.994,5.736 102.853,5.595 102.669,5.519 102.57,5.519 101.07,5.519 101.07,7.419 102.57,7.419 102.669,7.419
$Net0 on Top Layer "Top Layer-$Net0" (solid, pour order 2662): 128 vertices, not listed, extent 98.797,14.178 110.324,29.713
$Net7 on Top Layer "Top Layer-$Net7" (solid, pour order 2660): 156.747,35.003 156.747,23.315 155.86,22.428 142.649,22.428 141.939,23.138 141.939,26.948 141.378,27.508 137.823,27.508 137.113,28.218 137.113,34.927 137.823,35.636 156.114,35.636
$Net0 on Top Layer "Top Layer-$Net0 1" (solid, pour order 2658): 28 vertices, not listed, extent 84.816,24.338 87.959,27.549
$Net6 on Top Layer "Top Layer-$Net6 8" (solid, pour order 2656): 71.743,28.002 72.75,28.002 72.75,27.799 71.743,27.799 71.743,27.584 70.633,27.584 70.633,28.245 71.743,28.245
$Net6 on Top Layer "Top Layer-$Net6 9" (solid, pour order 2654): 88.574,27.711 87.304,27.711 87.304,28.372 88.574,28.372
$Net0 on Top Layer "Top Layer-$Net0 2" (solid, pour order 2652): 59 vertices, not listed, extent 94.751,31.407 100.591,34.762
$Net9 on Top Layer "Top Layer-$Net9" (solid, pour order 2650): 39 vertices, not listed, extent 128.223,28.179 136.859,40.716
$Net0 on Top Layer "Top Layer-$Net0 3" (solid, pour order 2648): 95 vertices, not listed, extent 104.276,28.964 110.87,39.898
$Net100 on Top Layer "Top Layer-$Net100 1" (solid, pour order 2646): 119.282,51.096 119.282,43.011 118.943,42.672 117.767,42.672 117.56,42.88 117.25,43.189 117.25,49.682 117.25,51.147 117.462,51.359 119.02,51.359
$Net0 on Top Layer "Top Layer-$Net0 4" (solid, pour order 2644): 66 vertices, not listed, extent 109.127,51.923 113.969,78.651
$Net8 on Top Layer "Top Layer-$Net8" (solid, pour order 2642): 30 vertices, not listed, extent 137.113,36.398 156.671,53.162
$Net0 on Top Layer "Top Layer-$Net0 5" (solid, pour order 2640): 89 vertices, not listed, extent 78.977,48.574 86.282,54.552
$Net157 on Top Layer "Top Layer-$Net157" (solid, pour order 2638): 17 vertices, not listed, extent 10.952,55.804 26.437,63.932
$Net158 on Top Layer "Top Layer-$Net158" (solid, pour order 2636): 26.437,81.966 26.437,79.934 26.437,76.124 13.229,76.124 12.467,75.362 12.467,70.536 14.499,68.504 14.499,66.98 10.952,66.98 10.952,79.69 11.705,80.442 22.881,80.442 24.405,81.966
$Net111 on Top Layer "Top Layer-$Net111" (solid, pour order 2634): 64.283,95.682 57.171,95.682 49.043,87.554 49.043,77.14 39.137,77.14 39.137,87.808 44.217,87.808 45.995,89.586 45.995,92.126 48.789,92.126 53.863,97.201 64.283,97.201
$Net2 on Top Layer "Top Layer-$Net2" (solid, pour order 2632): 17 vertices, not listed, extent 41.107,88.783 44.707,93.183
$Net116 on Top Layer "Top Layer-$Net116" (solid, pour order 2630): 61.32,91.135 59.669,91.135 59.669,91.796 61.32,91.796
$Net0 on Top Layer "Top Layer-$Net0 6" (solid, pour order 2628): 71 vertices, not listed, extent 92.859,57.55 106.044,93.482
$Net2 on Top Layer "Top Layer-$Net2 1" (solid, pour order 2626): 33 vertices, not listed, extent 39.899,88.824 45.741,96.952
$Net0 on Top Layer "Top Layer-$Net0 7" (solid, pour order 2624): 33 vertices, not listed, extent 109.229,96.968 111.149,116.937
$Net10 on Top Layer "Top Layer-$Net10 5" (solid, pour order 2622): 125.517,104.229 126.761,104.21 128.006,104.209 129.25,104.226 129.872,104.242 139.933,104.242 139.933,97.841 124.924,97.815 124.895,104.155 124.986,104.244
$Net116 on Top Layer "Top Layer-$Net116 1" (solid, pour order 2620): 70.658,102.286 71.861,102.286 71.861,101.625 70.963,101.625 70.311,100.974 70.311,100.245 70.514,100.042 70.514,99.212 69.727,99.212 69.727,100.974 69.202,101.498 67.365,101.498 67.365,102.489 70.455,102.489
$Net0 on Top Layer "Top Layer-$Net0 8" (solid, pour order 2618): 185 vertices, not listed, extent 34.824,99.523 77.485,122.093
$Net105 on Top Layer "Top Layer-$Net105" (solid, pour order 2616): 17 vertices, not listed, extent 138.129,102.184 156.671,114.376
$Net4 on Top Layer "Top Layer-$Net4" (solid, pour order 2614): 34.311,102.794 34.057,102.54 32.787,102.54 32.025,102.54 31.517,102.54 31.263,102.54 27.707,98.984 27.707,92.126 24.151,92.126 24.151,82.728 22.627,81.204 10.952,81.204 10.952,107.366 34.311,107.366
$Net110 on Top Layer "Top Layer-$Net110" (solid, pour order 2612): 40.661,110.414 35.073,110.414 33.041,108.382 10.952,108.382 10.952,118.796 40.661,118.796
$Net3 on Top Layer "Top Layer-$Net3 2" (solid, pour order 2610): 35 vertices, not listed, extent 32.533,74.092 68.093,120.32
$Net107 on Top Layer "Top Layer-$Net107" (solid, pour order 2608): 25 vertices, not listed, extent 128.731,106.248 137.113,119.456
$Net5 on Top Layer "Top Layer-$Net5" (solid, pour order 2606): 113.305,123.423 111.726,121.844 107.717,121.844 106.193,120.32 97.303,120.32 97.303,126.416 113.305,126.416
$Net109 on Top Layer "Top Layer-$Net109" (solid, pour order 2604): 33.295,128.194 36.343,125.146 38.883,125.146 38.883,122.606 26.691,122.606 26.691,123.114 26.691,124.892 28.723,126.924 28.723,136.322 33.295,136.322
$Net100 on Top Layer "Top Layer-$Net100 2" (solid, pour order 2602): 93.747,137.592 93.747,128.194 92.985,127.432 92.985,123.876 91.461,123.876 91.461,127.432 90.699,128.194 90.699,132.258 89.175,133.782 86.635,133.782 86.127,134.29 86.127,137.592 86.635,138.1 93.239,138.1
$Net100 on Top Layer "Top Layer-$Net100 3" (solid, pour order 2600): 120.197,126.788 120.197,125.104 119.959,124.866 115.837,124.866 115.472,125.231 115.472,126.763 115.811,127.102 119.883,127.102
$Net106 on Top Layer "Top Layer-$Net106" (solid, pour order 2598): 38 vertices, not listed, extent 138.155,114.859 156.697,131.75
no net on Top Overlay (solid): 52 vertices, not listed, extent 67.562,65.041 67.862,65.434
no net on Top Overlay (solid): 29 vertices, not listed, extent 66.246,65.018 66.5,65.226
no net on Top Overlay (solid): 23 vertices, not listed, extent 68.255,65.272 68.509,65.434
no net on Top Overlay (solid): 23 vertices, not listed, extent 71.187,65.272 71.441,65.434
no net on Top Overlay (solid): 29 vertices, not listed, extent 72.942,65.018 73.173,65.226
no net on Top Overlay (solid): 52 vertices, not listed, extent 74.258,65.041 74.581,65.434
no net on Top Overlay (solid): 29 vertices, not listed, extent 75.62,65.018 75.851,65.226
no net on Top Overlay (solid): 22 vertices, not listed, extent 76.567,65.272 76.821,65.434
no net on Top Overlay (solid): 27 vertices, not listed, extent 76.821,72.383 76.959,72.614
no net on Top Overlay (solid): 107 vertices, not listed, extent 76.659,72.037 77.167,72.706
no net on Top Overlay (solid): 131 vertices, not listed, extent 76.405,71.899 77.352,72.845
no net on Top Overlay (solid): 112 vertices, not listed, extent 70.194,73.33 70.91,74.254
no net on Top Overlay (solid): 111 vertices, not listed, extent 71.048,73.33 71.764,74.254
no net on Top Overlay (solid): 104 vertices, not listed, extent 69.594,73.399 70.471,74.069
no net on Top Overlay (solid): 103 vertices, not listed, extent 71.51,73.399 72.364,74.069
no net on Top Overlay (solid): 164 vertices, not listed, extent 68.901,73.976 70.01,75.339
no net on Top Overlay (solid): 166 vertices, not listed, extent 71.949,73.976 73.057,75.339
no net on Top Overlay (solid): 108 vertices, not listed, extent 71.048,74.254 71.995,75.316
no net on Top Overlay (solid): 109 vertices, not listed, extent 69.963,74.277 70.91,75.339
no net on Top Overlay (solid): 114 vertices, not listed, extent 71.048,75.454 71.995,76.539
no net on Top Overlay (solid): 164 vertices, not listed, extent 71.949,75.454 73.057,76.816
no net on Top Overlay (solid): 164 vertices, not listed, extent 68.901,75.477 70.01,76.816
no net on Top Overlay (solid): 108 vertices, not listed, extent 69.963,75.477 70.91,76.539
no net on Top Overlay (solid): 116 vertices, not listed, extent 70.194,76.516 70.91,77.463
no net on Top Overlay (solid): 111 vertices, not listed, extent 71.048,76.539 71.764,77.463
no net on Top Overlay (solid): 108 vertices, not listed, extent 69.594,76.701 70.471,77.394
no net on Top Overlay (solid): 105 vertices, not listed, extent 71.51,76.724 72.364,77.394
no net on Top Overlay (solid): 141.332,7.571 141.132,7.571 141.132,7.771 141.332,7.771
no net on Top Overlay (solid): 141.332,10.111 141.132,10.111 141.132,10.311 141.332,10.311
no net on Top Overlay (solid): 141.332,12.651 141.132,12.651 141.132,12.851 141.332,12.851
no net on Top Overlay (solid): 141.332,15.191 141.132,15.191 141.132,15.391 141.332,15.391
no net on Top Overlay (solid): 124.746,21.26 124.111,21.26 124.111,23.546 124.746,23.546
